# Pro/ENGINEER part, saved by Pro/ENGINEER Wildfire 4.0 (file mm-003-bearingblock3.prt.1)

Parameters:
  METRIC = "NO"

Other parameters: PITCH, DRILL_POINT_ANGLE, DRILL_DEPTH, DRILL_DIAMETER, THREAD_DIAMETER, THREADS_PER_INCH, THREAD_DEPTH, THREAD_LENGTH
